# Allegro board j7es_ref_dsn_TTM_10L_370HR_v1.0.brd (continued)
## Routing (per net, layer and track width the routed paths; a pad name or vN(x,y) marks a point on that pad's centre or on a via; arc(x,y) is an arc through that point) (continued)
MCU_OSPI0_D2: length 34.5
  TOP w0.229: R161.2 U24.C4 v1(78.75,45.46) ; v1(94.25,64.95) 94.65,65.35 U9.G20
  L7-SIGNAL w0.097: v1(94.25,64.95) 93.88,65.31 93.13,65.31 93.02,65.19 93.02,59.22 90.81,57.01 84.45,57.01 78.34,50.9 78.34,45.87 v1(78.75,45.46)
  BOTTOM w0.229: U24.C4 v1(78.75,45.46)
MCU_OSPI0_D3: length 37.6
  TOP w0.229: v1(78.75,44.46) 78.22,43.93 77.75,43.93 77.62,43.8 R158.2 ; v1(94.25,64.15) 94.25,64.15 U9.F20
  L9-SIGNAL w0.097: v1(78.75,44.46) 79.28,43.93 82.04,43.93 82.42,43.55 84.36,43.55 86.26,45.46 89.79,45.46 96.01,51.68 96.01,58.36 95.45,58.92 95.45,63.49 95.16,63.78 94.61,63.78 v1(94.25,64.15)
  BOTTOM w0.229: U24.D4 v1(78.75,44.46)
MCU_OSPI0_D4: length 35.3
  TOP w0.229: U9.F21 93.45,64.15 v1(93.45,64.15) ; R162.2 77,44.46 v1(77.75,44.46)
  L7-SIGNAL w0.097: v1(77.75,44.46) 78.23,44.95 78.87,44.95 79.25,45.33 79.25,48 80.64,49.39 84.84,49.39 85.22,49.01 90.3,49.01 92.96,51.68 92.96,58.28 93.83,59.14 93.83,63.8 93.48,64.15 v1(93.45,64.15)
  BOTTOM w0.229: U24.D5 v1(77.75,44.46)
MCU_OSPI0_D5: length 31
  TOP w0.229: U9.E21 93.85,63.75 v1(93.45,63.35) ; v1(79.75,43.46) 79.75,42.81 R156.2
  L5-PWR/GND w0.097: v1(93.45,63.35) 93.01,62.9 93.01,61.9 93.01,61.89 93.01,61.6 93.01,61.6 93.01,59.21 89.75,55.95 89.75,53.75 89.28,53.29 89.28,50.79 85.72,47.23 85.72,44.31 84.45,43.04 80.17,43.04 v1(79.75,43.46)
  BOTTOM w0.229: U24.E3 v1(79.75,43.46)
MCU_OSPI0_D6: length 28
  TOP w0.229: v1(92.65,60.95) 93.05,61.35 U9.B22 ; R150.2 81.34,44.06 v1(80.75,43.46)
  L5-PWR/GND w0.097: v1(92.65,60.95) 92.21,60.5 92.21,59.18 89.41,56.38 89.41,53.97 88.77,53.33 88.77,50.79 85.34,47.36 85.34,44.57 84.2,43.42 82.8,43.42 82.3,43.93 81.22,43.93 v1(80.75,43.46)
  BOTTOM w0.229: U24.E2 v1(80.75,43.46)
MCU_OSPI0_D7: length 33.5
  TOP w0.229: v1(81.75,43.46) 81.75,43.06 81.89,42.91 82.38,42.91 R151.2 ; v1(93.45,64.95) 93.45,64.95 U9.G21
  L7-SIGNAL w0.097: v1(81.75,43.46) 82.14,43.46 82.24,43.36 86.04,43.36 93.85,51.17 93.85,56.5 95.48,58.14 95.48,62.63 95.2,62.91 94.97,62.91 94.68,63.19 94.68,63.5 94.74,63.56 94.74,63.87 94.61,64 94.61,64.3 94.4,64.51 93.88,64.51 v1(93.45,64.95)
  BOTTOM w0.229: U24.E1 v1(81.75,43.46)
MCU_OSPI0_DQS: length 22.8
  TOP w0.229: v1(93.45,62.55) 93.45,62.55 U9.D21 ; R152.2 84.11,47.87 v1(84.71,47.27)
  L2-SIGNAL w0.097: v1(84.71,47.27) 84.71,50.47 85.79,51.55 87.69,51.55 89.66,53.52 89.66,55.93 91.06,57.33 91.06,59.17 91.48,59.6 91.48,60.3 91.7,60.51 92,60.51 92.28,60.79 92.28,61.1 92.5,61.31 92.8,61.31 93.08,61.59 93.08,62.18 v1(93.45,62.55)
MCU_OSPI0_ECC_FAIL: length 23.2
  TOP w0.229: U9.B23 91.85,60.95 v1(91.85,60.95) ; R164.1 v1(75.55,47.73)
  L9-SIGNAL w0.097: v1(75.55,47.73) 75.55,48.62 85.22,58.28 89.79,58.28 91.44,59.93 91.44,60.54 v1(91.85,60.95)
MCU_OSPI0_LBCLKO: length 20.4
  L9-SIGNAL w0.097: v1(92.38,56.8) 93.05,56.13 93.05,54.43 92.46,53.84 85.85,53.84 81.25,49.23 v1(81.25,48.09)
  BOTTOM w0.229: R264.2 92.39,56.79 v1(92.38,56.8) ; U24.B1 v1(81.25,48.09) 81.28,48.12 R3140.1
MCU_OSPI0_RESET_OUT0: length 1.4
  TOP w0.229: R137.1 R108.1
MCU_OSPI0_RESET_OUT0_R: length 2.7
  TOP w0.229: R108.2 70.48,48.2 R114.1 70.56,47.67 70.61,47.61 U18.2
MCU_OSPI1_CLK: length 0.9
  BOTTOM w0.229: R240.2 79.97,61.67 TPX68.1
MCU_OSPI1_CLK_R: length 13.7
  TOP w0.229: U9.F22 93.05,64.55 v1(92.65,64.15)
  L9-SIGNAL w0.097: v1(92.65,64.15) 92.26,64.54 88.46,64.54 88.22,64.3 88.22,63.99 88,63.78 83.47,63.78 v1(81.91,62.22)
  BOTTOM w0.229: R240.1 v1(81.91,62.22)
MCU_OSPI1_CS0: length 39.3
  TOP w0.229: U9.C22 92.66,61.75 v1(92.65,61.75)
  L7-SIGNAL w0.097: v1(92.65,61.75) 92.65,61.68 92.21,61.24 92.21,59.18 90.42,57.39 84.2,57.39 80.39,53.58 76.2,53.58 73.53,50.92 62.74,50.92 62.23,50.41 62.23,49.14 TPX95.1
MCU_OSPI1_D0: length 31.3
  TOP w0.229: U9.D22 93.05,62.95 v1(92.65,62.55)
  L7-SIGNAL w0.097: v1(92.65,62.55) 92.21,62.11 90.9,62.11 90.68,61.9 90.68,59.18 89.75,58.24 83.79,58.24 80,54.45 75.79,54.45 73.53,52.19 TPX168.1
MCU_OSPI1_D1: length 33.8
  TOP w0.229: v1(92.65,64.95) 93.05,65.35 U9.G22
  L9-SIGNAL w0.097: v1(92.65,64.95) 92.52,64.95 92.09,65.38 88.5,65.38 88.22,65.1 88.22,64.79 88,64.58 83.69,64.58 72.06,52.95 66.04,52.95 TPX93.1
MCU_OSPI1_D2: length 34.1
  TOP w0.229: v1(91.85,62.55) 92.25,62.95 U9.D23
  L9-SIGNAL w0.097: v1(91.85,62.55) 91.41,62.11 90.9,62.11 90.63,61.84 90.63,59.98 89.44,58.79 84.66,58.79 75.52,49.65 66.55,49.65 TPX21.1
MCU_OSPI1_D3: length 39.9
  TOP w0.229: v1(91.85,61.75) 91.85,61.75 U9.C23
  L7-SIGNAL w0.097: v1(91.85,61.75) 91.85,61.66 91.44,61.25 91.44,59.17 90.04,57.77 83.95,57.77 80.19,54.02 76,54.02 73.14,51.16 61.46,51.16 60.96,50.66 60.96,49.14 TPX121.1
MCU_PERIPH_RSTZ: length 1.5
  TOP w0.229: R109.1 TPX67.1
MCU_PERIPH_RSTZ_R: length 2.6
  TOP w0.229: R109.2 71.63,48.2 R115.1 71.55,47.67 71.56,47.65 U18.1
MCU_PORZ: length 31.1
  TOP w0.229: U9.H23 92.25,66.15 v1(91.85,65.75)
  L5-PWR/GND w0.097: TPX166.1 66.29,59.43 76.2,59.43 79.38,62.6 83.31,62.6 83.82,62.09 86.89,62.09 86.98,62.19 88,62.19 88.21,62.4 88.21,62.61 88.58,62.99 88.8,62.99 89.09,63.28 89.09,63.49 89.3,63.7 89.51,63.7 89.81,64 89.81,64.21 90.1,64.5 90.31,64.5 90.61,64.8 90.61,65.01 90.9,65.3 91.41,65.3 v1(91.85,65.75)
MCU_PORZ_OUT: length 54
  TOP w0.229: R124.1 v1(40.77,52.82) ; v1(87.85,60.95) 87.85,60.95 U9.B28
  L2-SIGNAL w0.097: v1(40.77,52.82) 44.07,52.82 45.72,51.17 48.13,51.17 50.26,53.29 55.21,53.29 56.52,54.6 78.87,54.6 84.84,60.57 87.47,60.57 v1(87.85,60.95)
MCU_RESETSTATZ: length 54.3
  TOP w0.229: TP116.1 TPX92.1 R113.1 ; U9.C27 89.05,62.15 v1(88.65,61.75)
  L4-SIGNAL w0.097: TPX92.1 41.78,60.57 54.55,60.57 54.87,60.25 59.75,60.25 60.83,61.33 74.42,61.33 75.06,60.7 84.07,60.7 84.75,61.38 88.26,61.38 88.63,61.75 v1(88.65,61.75)
MCU_RESETZ: length 56.1
  TOP w0.229: v1(87.85,62.55) 87.85,62.55 U9.D28
  L2-SIGNAL w0.097: TPX193.1 36.55,53.94 53.82,53.94 54.35,54.47 55.37,54.47 56.01,55.11 78.42,55.11 85.17,61.85 86.64,61.85 86.9,62.11 87.41,62.11 v1(87.85,62.55)
MCU_RGMII1_INT#: length 29.4
  TOP w0.229: U9.E25 90.65,63.75 v1(90.25,63.35)
  L9-SIGNAL w0.097: v1(90.25,63.35) 89.85,63.74 88.46,63.74 88.22,63.5 88.22,63.19 88,62.98 84.6,62.98 74.19,52.57 67.99,52.57 67.98,52.58 66.94,52.58 TPX48.1
MCU_RGMII1_RD0: length 35.8
  TOP w0.229: U9.B24 91.45,61.35 v1(91.05,60.95)
  L5-PWR/GND w0.097: TPX80.1 63.34,47.07 66.51,47.07 67.69,48.25 67.69,48.8 69.17,50.28 76.33,50.28 83.31,57.27 88.39,57.27 90.61,59.49 90.61,60.51 v1(91.05,60.95)
MCU_RGMII1_RD1: length 34.3
  TOP w0.229: v1(91.05,60.14) 91.05,60.14 U9.A24
  L5-PWR/GND w0.097: v1(91.05,60.14) 91.05,59.16 88.77,56.89 83.57,56.89 76.33,49.65 68.83,49.65 68.07,48.88 68.07,48.12 66.81,46.86 66.01,46.86 66.01,46.86 65.49,46.86 65.49,46.86 64.4,46.86 TPX87.1
MCU_RGMII1_RD2: length 36.4
  TOP w0.229: v1(91.05,62.55) 91.05,62.55 U9.D24
  L5-PWR/GND w0.097: TPX88.1 63.25,47.87 65.66,47.87 65.91,48.12 65.91,48.76 66.42,49.27 67.06,49.27 71.12,53.33 77.09,53.33 82.17,58.41 87.63,58.41 89.09,59.87 89.09,60.29 89.3,60.5 89.72,60.5 89.89,60.67 89.89,61.09 90.1,61.3 90.4,61.3 90.44,61.34 90.44,61.38 90.69,61.63 90.69,62.19 v1(91.05,62.55)
MCU_RGMII1_RD3: length 35.5
  TOP w0.229: U9.A25 90.25,60.14 v1(90.25,60.14)
  L5-PWR/GND w0.097: TPX107.1 62.28,47.28 66.29,47.28 67.26,48.26 67.26,48.71 69.27,50.72 76.25,50.72 83.19,57.65 88.14,57.65 90.25,59.76 v1(90.25,60.14)
MCU_RGMII1_RX_CTL: length 32.7
  TOP w0.229: U9.C25 90.65,62.15 v1(90.25,61.75)
  L5-PWR/GND w0.097: TPX61.1 65.28,49.65 66.93,49.65 71.37,54.09 77.22,54.09 82.04,58.92 87.25,58.92 88.27,59.93 88.27,60.27 88.5,60.5 88.71,60.5 89.01,60.8 89.01,61.06 89.34,61.39 89.89,61.39 v1(90.25,61.75)
MCU_RGMII1_RXC: length 38.6
  TOP w0.229: U9.C24 91.05,61.75 v1(91.05,61.75)
  L5-PWR/GND w0.097: TPX64.1 61.34,47.61 65.7,47.61 66.12,48.04 66.12,48.67 66.38,48.93 67.02,48.93 70.07,51.99 76.63,51.99 82.68,58.03 87.84,58.03 89.81,59.99 89.81,60.22 90.1,60.51 90.32,60.51 90.61,60.79 90.61,61.31 v1(91.05,61.75)
MCU_RGMII1_TD0: length 59.8
  TOP w0.229: U9.B25 90.65,61.35 v1(90.25,60.95)
  L2-SIGNAL w0.097: v1(90.25,60.95) 89.88,60.58 89.88,58.38 87.76,56.25 86.11,56.25 82.68,52.82 59.69,52.82 57.66,50.79 51.05,50.79 49.53,49.27 37.72,49.27 TPX106.1
MCU_RGMII1_TD1: length 59.7
  TOP w0.229: v1(89.45,60.14) 89.85,60.54 U9.A26
  L2-SIGNAL w0.097: v1(89.45,60.14) 89.45,58.7 87.88,57.14 85.09,57.14 81,53.05 59.41,53.05 57.4,51.04 50.67,51.04 49.15,49.52 38.61,49.52 37.97,50.15 36.58,50.15 TPX108.1
MCU_RGMII1_TD2: length 61.2
  TOP w0.229: v1(88.65,60.14) 89.05,60.54 U9.A27
  L2-SIGNAL w0.097: TPX131.1 34.67,50.79 38.23,50.79 38.86,50.15 48.64,50.15 50.17,51.68 55.24,51.68 56.64,53.08 57.79,53.08 58.29,53.58 80.52,53.58 84.71,57.77 87.38,57.77 88.65,59.05 v1(88.65,60.14)
MCU_RGMII1_TD3: length 55.2
  TOP w0.229: v1(87.85,60.14) 87.85,60.14 U9.A28
  L2-SIGNAL w0.097: v1(87.85,60.14) 85.05,60.14 79.25,54.35 56.9,54.35 54.88,52.33 49.8,52.33 48.39,50.92 45.34,50.92 44.83,51.42 40.77,51.42 40.64,51.55 TPX187.1
MCU_RGMII1_TX_CTL: length 58.5
  TOP w0.229: v1(88.65,60.95) 88.65,60.95 U9.B27
  L2-SIGNAL w0.097: TPX156.1 36.47,51.15 44.47,51.15 45.08,50.54 48.51,50.54 50.08,52.11 55.16,52.11 57.02,53.96 80.26,53.96 84.58,58.28 87,58.28 88.27,59.55 88.27,60.56 v1(88.65,60.95)
MCU_RGMII1_TXC: length 61.5
  TOP w0.229: U9.B26 89.85,61.35 v1(89.45,60.95)
  L2-SIGNAL w0.097: TPX105.1 35.69,50.54 38.1,50.54 38.86,49.77 48.77,49.77 50.42,51.42 57.4,51.42 59.31,53.33 80.64,53.33 84.71,57.39 87.63,57.39 89.01,58.78 89.01,60.51 v1(89.45,60.95)
MCU_SAFETY_ERRZ: length 1.5
  TOP w0.229: U27.18 126.59,99.15 126.49,99.05 ; R120.2 v1(84.58,53.84)
MCU_UART0_CTS#: length 53.9
  TOP w0.229: U9.H29 87.05,65.75 v1(87.05,65.75)
  L2-SIGNAL w0.097: TPX214.1 43.81,57.27 43.94,57.14 48.89,57.14 49.56,57.8 54.64,57.8 54.99,58.16 61.15,58.16 64.2,61.2 78.74,61.2 80.9,63.36 83.44,63.36 85.82,65.75 v1(87.05,65.75)
MCU_UART0_RTS#: length 29.3
  TOP w0.229: U9.J27 89.05,66.95 v1(88.65,66.55)
  L5-PWR/GND w0.097: TPX215.1 63.88,61.58 75.69,61.58 77.64,63.53 83.48,63.53 85.34,65.39 88,65.39 88.21,65.6 88.21,66.1 v1(88.65,66.55)
MCU_UART0_RXD: length 56.5
  TOP w0.229: v1(87.85,65.75) 87.85,65.75 U9.H28
  L2-SIGNAL w0.097: v1(87.85,65.75) 87.48,66.11 85.68,66.11 83.31,63.74 80.9,63.74 78.74,61.58 61.72,61.58 59.31,59.17 48.64,59.17 46.99,57.52 45.15,57.52 45.13,57.5 44.79,57.5 44.77,57.52 38.73,57.52 38.35,57.9 36.7,57.9 TPX258.1
MCU_UART0_TXD: length 54.3
  TOP w0.229: v1(87.05,64.95) 87.45,65.35 U9.G29
  L2-SIGNAL w0.097: TPX319.1 45.24,56 45.49,56.25 53.34,56.25 53.47,56.12 54.1,56.12 54.82,56.84 61.93,56.84 62.23,57.14 62.23,57.52 62.74,58.03 75.56,58.03 77.6,60.06 80.31,60.06 82.85,62.6 83.69,62.6 86.04,64.95 v1(87.05,64.95)
MDIO0_MDC: length 64.4
  TOP w0.191: U9.V24 91.45,74.15 v1(91.05,74.55)
  TOP w0.229: v1(52.7,45.46) 51.94,44.69 49.64,44.69 49.61,44.67 U2011.1
  L5-PWR/GND w0.097: v1(91.05,74.55) 90.7,74.2 90.7,73.16 89.81,72.27 89.81,72 89.55,71.74 83.95,71.74 81.96,69.76 62.83,69.76 59.99,66.92 58.93,66.92 58.29,66.28 58.29,58.92 56.9,57.52 56.9,54.35 56.52,53.96 56.52,49.27 v1(52.7,45.46)
MDIO0_MDIO: length 66.4
  TOP w0.191: U9.V26 89.85,74.15 v1(89.45,74.55)
  TOP w0.229: U2011.36 v1(50.9,43.77)
  L5-PWR/GND w0.097: v1(89.45,74.55) 89.01,74.11 86.56,74.11 86.11,73.65 80.91,73.65 79.64,72.38 76.96,72.38 76.45,72.89 70.74,72.89 69.47,74.16 60.32,74.16 56.13,69.97 56.13,59.81 54.86,58.54 54.86,55.11 51.58,51.83 51.58,48.02 50.93,47.36 50.93,44.18 50.9,44.15 v1(50.9,43.77)
MLB0_MLBCLK_N: length 63.6
  TOP w0.122: v1(109.45,80.15) 109.05,79.75 U9.AE2
  L9-SIGNAL w0.076: v1(109.45,80.15) 109.45,80.1 109.67,79.88 109.78,79.88 109.88,79.97 109.88,80.3 110.08,80.51 110.52,80.51 110.75,80.74 110.75,80.95 113.3,83.51 122.26,83.51 122.69,83.94 127.81,83.94 128.57,83.17 131.73,83.17 132.29,82.62 137.85,82.62 141.91,78.55 162.98,78.55 164.13,79.7 167.06,79.7 167.13,79.77 TPX351.1
MLB0_MLBCLK_P: length 63.4
  TOP w0.122: U9.AD2 109.05,78.95 v1(109.45,79.35)
  L9-SIGNAL w0.076: v1(109.45,79.35) 109.64,79.35 110.06,79.77 110.39,79.77 110.62,80 110.62,80.32 110.95,80.65 110.95,80.87 113.39,83.3 122.34,83.3 122.77,83.73 127.72,83.73 128.49,82.97 131.65,82.97 132.21,82.41 137.76,82.41 141.83,78.35 163.07,78.35 164.21,79.49 166.88,79.49 167.13,79.24 TPX352.1
MLB0_MLBDAT_N: length 66.3
  TOP w0.122: U9.AD3 108.25,78.95 v1(108.65,79.35)
  L9-SIGNAL w0.076: v1(108.65,79.35) 109.01,79.71 109.01,80.39 109.03,80.41 109.06,80.47 109.06,80.48 109.1,80.55 109.14,80.59 109.6,80.59 109.81,80.8 109.81,81.1 109.91,81.19 109.99,81.19 110.2,81.39 110.4,81.39 110.61,81.6 110.61,81.61 110.65,81.65 110.65,81.78 114.08,85.21 127.86,85.21 129.2,83.86 137.58,83.86 142.21,79.24 162.05,79.24 164.87,82.06 167.06,82.06 167.13,81.98 TPX333.1
MLB0_MLBDAT_P: length 68.2
  TOP w0.122: U9.AC3 108.25,78.15 v1(108.65,78.55)
  L9-SIGNAL w0.076: TPX334.1 167.13,82.34 167.06,82.26 164.79,82.26 161.97,79.44 142.29,79.44 137.67,84.06 129.29,84.06 127.94,85.41 114,85.41 110.55,81.96 110.55,81.96 110.4,82.11 110.11,82.11 109.9,81.9 109.9,81.6 109.91,81.59 109.91,81.4 109.82,81.4 109.73,81.31 109.31,81.31 109.1,81.1 109.1,80.8 109.09,80.8 109.06,80.8 108.93,80.67 108.9,80.61 108.88,80.57 108.87,80.57 108.84,80.51 108.51,80.51 108.3,80.3 108.3,78.91 v1(108.65,78.55)
MLB0_MLBSIG_N: length 62
  TOP w0.122: v1(110.25,78.55) 109.85,78.15 U9.AC1
  L9-SIGNAL w0.076: v1(110.25,78.55) 110.55,78.85 110.79,78.85 111.25,79.31 111.25,80.12 112.4,81.27 121.95,81.27 122.83,82.15 131.17,82.15 131.61,81.7 137.2,81.7 141.44,77.46 162.69,77.46 163.17,76.98 167.06,76.98 167.13,76.9 TPX354.1
MLB0_MLBSIG_P: length 62
  TOP w0.122: v1(110.25,79.35) 109.85,78.95 U9.AD1
  L9-SIGNAL w0.076: TPX353.1 167.13,77.26 167.06,77.18 163.25,77.18 162.77,77.66 141.53,77.66 137.29,81.9 131.7,81.9 131.25,82.35 122.75,82.35 121.87,81.47 112.32,81.47 111.05,80.2 111.05,79.4 110.7,79.05 110.55,79.05 v1(110.25,79.35)
MMC0_CALPAD: length 1.4
  TOP w0.191: U9.AE1 109.85,79.75 v1(110.25,80.15)
  BOTTOM w0.229: R204.2 110.95,80.43 110.53,80.43 v1(110.25,80.15)
MMC0_CLK: length 41
  TOP w0.191: U9.AF1 110.25,80.94 v1(110.25,80.95)
  L5-PWR/GND w0.097: v2(146.81,85.97) 144.65,83.81 122.68,83.81 122.05,83.17 121.96,83.17 121.96,83.17 121.79,83.17 121.79,83.17 119.38,83.17 117.6,81.4 111.51,81.4 111.06,80.95 v1(110.25,80.95)
  BOTTOM w0.127: R1204.2 R1203.1 v2(146.81,85.97)
MMC0_CMD: length 43.7
  TOP w0.191: v1(108.65,80.15) 108.65,80.14 U9.AE3
  TOP w0.229: U1017.P5 v2(147.66,86.21)
  L5-PWR/GND w0.097: v2(147.66,86.21) 143.74,82.29 121.54,82.29 120.4,81.14 111.72,81.14 111.08,80.51 109.01,80.51 v1(108.65,80.15)
  BOTTOM w0.127: R1200.2 147.7,86.16 v2(147.66,86.21)
MMC0_DAT0: length 47.4
  TOP w0.191: v1(109.45,81.75) 109.45,81.74 U9.AG2
  TOP w0.229: U1017.K2 v2(151.66,89.21)
  L5-PWR/GND w0.097: v1(109.45,81.75) 109.86,82.16 111,82.16 114.13,85.29 123.87,85.29 124.55,85.97 143.76,85.97 v1(146.56,88.76)
  L9-SIGNAL w0.097: v1(146.56,88.76) 151.21,88.76 v2(151.66,89.21)
  BOTTOM w0.127: v2(151.66,89.21) 151.64,89.23 151.64,90.03
MMC0_DAT1: length 44.3
  TOP w0.191: v1(110.25,82.55) 110.25,82.54 U9.AH1
  TOP w0.229: U1017.N2 v2(148.66,89.21)
  L5-PWR/GND w0.097: v1(110.25,82.55) 111.01,82.55 115.44,86.98 124.08,86.98 124.84,86.22 143.25,86.22 146.74,89.71 148.16,89.71 v2(148.66,89.21)
  BOTTOM w0.127: R1197.2 148.72,89.27 v2(148.66,89.21)
MMC0_DAT2: length 50.8
  TOP w0.191: U9.AG3 108.65,81.74 v1(108.65,81.75)
  TOP w0.229: U1017.K3 v2(151.66,88.21)
  L5-PWR/GND w0.097: v1(108.65,81.75) 109.1,82.19 109.1,82.7 109.3,82.91 109.59,82.91 109.98,83.3 111,83.3 115.19,87.49 125.3,87.49 125.43,87.37 135.89,87.37 136.53,88 143.51,88 146.05,90.54 150.4,90.54 151.13,89.81 151.13,88.74 v2(151.66,88.21)
  BOTTOM w0.127: 151.64,87.37 151.64,88.19 v2(151.66,88.21)
MMC0_DAT3: length 50.4
  TOP w0.191: U9.AF4 107.85,80.94 v1(107.85,80.95)
  TOP w0.229: U1017.N3 v2(148.66,88.21)
  L5-PWR/GND w0.097: v1(148.08,90.92) 145.92,90.92 143.38,88.38 130.68,88.38 130.01,87.7 115.1,87.7 114.98,87.58 111.21,83.81 109.35,83.81 109.01,83.47 109.01,83.2 108.8,82.99 108.53,82.99 108.21,82.67 108.21,81.31 v1(107.85,80.95)
  L7-SIGNAL w0.097: v2(148.66,88.21) 148.08,88.79 v1(148.08,90.92)
  BOTTOM w0.127: v2(148.66,88.21) 148.72,88.15 R1201.2
MMC0_DAT4: length 45.2
  TOP w0.191: U9.AE5 107.05,80.14 v1(107.05,80.15)
  TOP w0.229: U1017.N8 v2(148.66,82.2)
  L5-PWR/GND w0.097: v1(107.05,80.15) 107.5,79.71 110.71,79.71 111.89,80.89 120.52,80.89 121.67,82.03 145.16,82.03 145.41,81.78 148.23,81.78 v2(148.66,82.2)
  BOTTOM w0.127: v2(148.66,82.2) 148.84,82.39 R1196.2
MMC0_DAT5: length 55.9
  TOP w0.191: v1(108.65,80.95) 108.65,80.94 U9.AF3
  TOP w0.229: U1017.K8 v2(151.66,82.2)
  L5-PWR/GND w0.097: v1(108.65,80.95) 109.1,81.39 109.1,81.9 109.3,82.11 109.55,82.11 109.9,82.45 109.9,82.83 110.05,82.99 111.15,82.99 115.4,87.24 125.26,87.24 125.34,87.16 136.61,87.16 137.2,87.75 144.02,87.75 146.43,90.16 148.84,90.16 149.22,89.78 149.22,88.51 150.11,87.62 150.11,85.71 151.66,84.17 v2(151.66,82.2)
  BOTTOM w0.127: R1190.2 151.51,82.35 v2(151.66,82.2)
MMC0_DAT6: length 47.7
  TOP w0.191: v1(110.25,81.75) 110.25,81.74 U9.AG1
  TOP w0.229: U1017.N9 v2(148.66,81.2)
  L5-PWR/GND w0.097: v1(146.81,87.11) 145.8,87.11 144.4,85.71 124.59,85.71 123.96,85.08 114.3,85.08 110.97,81.75 v1(110.25,81.75)
  L7-SIGNAL w0.097: v2(148.66,81.2) 148.21,81.65 148.21,84.57 147.22,85.56 147.22,86.71 v1(146.81,87.11)
  BOTTOM w0.127: v2(148.66,81.2) 148.59,81.14 R1198.2
MMC0_DAT7: length 50.5
  TOP w0.191: U9.AF2 109.45,80.94 v1(109.45,80.95)
  TOP w0.229: U1017.K9 v2(151.66,81.2)
  L5-PWR/GND w0.097: v1(109.45,80.95) 109.81,81.31 110.91,81.31 111.25,81.65 117.35,81.65 119.08,83.39 121.88,83.39 122.55,84.06 124.46,84.06 125.35,84.95 144.53,84.95 146.18,86.6 147.48,86.6 147.49,86.61 147.83,86.61 149.35,85.08 149.35,82.54 150.24,81.65 151.21,81.65 v2(151.66,81.2)
  BOTTOM w0.127: v2(151.66,81.2) 151.64,81.18 R1191.2
MMC0_DS: length 51.2
  TOP w0.191: U9.AE4 107.85,80.14 v1(107.85,80.15)
  L5-PWR/GND w0.097: v1(107.85,80.15) 107.5,80.51 107.5,82.72 107.77,82.99 108,82.99 108.21,83.2 108.21,83.44 108.97,84.19 110.72,84.19 114.45,87.91 129.73,87.91 130.42,88.61 142.85,88.61 145.54,91.3 v1(150.88,91.3)
  BOTTOM w0.229: R3142.1 v1(150.88,91.3)
MMC1_CLK: length 23.7
  TOP w0.229: U9.P25 90.65,70.95 v1(90.25,70.55)
  L7-SIGNAL w0.097: TPX62.1 70.99,68.32 71.63,68.95 77.95,68.95 78.79,68.11 82.6,68.11 84.58,70.09 86.88,70.09 86.9,70.11 87.2,70.11 87.22,70.09 87.68,70.09 87.7,70.11 88,70.11 88.02,70.09 88.48,70.09 88.5,70.11 88.8,70.11 88.82,70.09 89.28,70.09 89.3,70.11 89.6,70.11 89.62,70.09 89.79,70.09 90.01,70.32 90.02,70.32 v1(90.25,70.55)
MMC1_CMD: length 22.5
  TOP w0.229: U9.R29 87.45,71.75 v1(87.05,71.35)
  L7-SIGNAL w0.097: TPX86.1 69.72,68.19 71.12,69.59 83.06,69.59 84.82,71.35 v1(87.05,71.35)
MMC1_DAT0: length 32.9
  TOP w0.229: U9.R24 91.06,71.35 v1(91.05,71.35)
  L7-SIGNAL w0.097: TPX136.1 66.55,66.79 71.46,71.7 81.62,71.7 82.64,72.72 86.74,72.72 86.74,72.72 90.34,72.72 90.68,72.38 90.68,71.72 v1(91.05,71.35)
MMC1_DAT1: length 26
  TOP w0.229: U9.P24 91.06,70.55 v1(91.05,70.55)
  L7-SIGNAL w0.097: TPX162.1 70.48,65.39 70.48,68.32 71.5,69.33 83.19,69.33 84.77,70.91 90.68,70.91 v1(91.05,70.55)
MMC1_DAT2: length 27
  TOP w0.229: U9.R25 90.65,71.75 v1(90.25,71.35)
  L7-SIGNAL w0.097: TPX111.1 69.09,66.79 69.09,68.82 71.75,71.49 82.93,71.49 83.82,72.38 86.61,72.38 86.75,72.51 89.6,72.51 89.82,72.3 89.82,71.78 v1(90.25,71.35)
MMC1_DAT3: length 26.1
  TOP w0.229: U9.R26 89.46,71.35 v1(89.45,71.35)
  L7-SIGNAL w0.097: TPX85.1 69.47,65.9 69.47,68.57 70.74,69.84 82.68,69.84 84.55,71.72 89.08,71.72 v1(89.45,71.35)
MMC1_SDCD/PCIE2_CLKREQN: length 35.9
  TOP w0.229: R86.2 TPX189.1 ; U9.P23 92.25,70.95 v1(91.85,70.55)
  BOTTOM w0.127: v1(91.85,70.55) 91.45,70.15 83.24,70.15 82.3,69.2 61.98,69.2 61.37,69.81 58.58,69.81 TPX189.1
Net_12: length 0.6
  TOP w0.191: 105.85,68.55 v1(106.25,68.15)
Net_13: length 0.6
  TOP w0.191: 105.85,70.15 v1(106.25,69.75)
Net_14: length 0.6
  TOP w0.229: 90.65,70.14 90.25,69.75 v1(90.25,69.75)
Net_15: length 0.6
  TOP w0.229: 89.05,71.74 88.66,71.35 v1(88.65,71.35)
Net_16: length 0.6
  TOP w0.191: 87.45,82.94 v1(87.05,83.34)
Net_17: length 0.6
  TOP w0.229: 89.85,70.94 89.85,70.95 v1(89.45,70.55)
Net_18: length 0.6
  TOP w0.191: v1(107.85,79.35) 107.45,78.95 107.45,78.94
Net_19: length 0.6
  TOP w0.229: v1(95.85,63.35) 96.25,63.74 96.25,63.74
Net_20: length 0.6
  TOP w0.229: 96.25,64.54 96.25,64.55 v1(95.85,64.15)
Net_21: length 0.6
  TOP w0.229: v1(103.05,64.95) 102.65,65.35 102.65,65.34
Net_22: length 0.6
  TOP w0.229: 101.85,64.54 v1(102.25,64.15)
Net_23: length 0.6
  TOP w0.191: 105.85,64.54 v1(106.25,64.15)
Net_24: length 0.6
  TOP w0.191: 105.85,63.74 v1(106.25,63.35)
Net_25: length 0.6
  TOP w0.229: v1(103.85,64.95) 103.45,65.35 103.45,65.34
Net_26: length 0.6
  TOP w0.229: 102.65,64.54 v1(103.05,64.15)
Net_33: length 2.9
  TOP w0.119: v1(118.49,21.52) 118.32,21.34 117.87,21.34 117.58,21.63 117.01,21.63 116.73,21.35 116.73,20.74 116.6,20.6
Net_34: length 2.7
  TOP w0.119: 117.15,20.6 117,20.76 117,21.24 117.11,21.36 117.47,21.36 117.76,21.08 118.37,21.08 118.49,20.96 v1(118.49,20.67)
Net_256: length 4.5
  TOP w0.119: 116.6,19.38 116.64,19.33 arc(116.71,19.24) 116.73,19.13 116.73,18.85 arc(116.71,18.74) 116.64,18.64 116.31,18.31 116.67,17.96 arc(116.69,17.93) 116.71,17.9 arc(116.71,17.88) 116.71,17.86 116.71,17.75 arc(116.82,17.48) 117.09,17.37 117.67,17.37 arc(117.75,17.34) 117.79,17.25 117.79,17.04 arc(117.78,17) 117.75,16.96 117.3,16.5 arc(117.24,16.41) 117.22,16.31
Net_257: length 4.5
  TOP w0.119: 117.15,19.38 117.13,19.35 arc(117.03,19.2) 116.99,19.03 116.99,18.86 arc(117.02,18.73) 117.09,18.62 117.37,18.35 117.37,18.31 117.01,17.96 arc(116.98,17.91) 116.97,17.86 116.97,17.75 arc(117,17.67) 117.09,17.63 117.67,17.63 arc(117.94,17.52) 118.05,17.25 118.05,16.98 arc(118.05,16.93) 118.06,16.88 arc(118.1,16.79) 118.16,16.72 118.57,16.31
Net_894: length 0.7
  BOTTOM w0.229: 77.25,46.96 v1(77.75,46.46)
Net_952: length 0.6
  TOP w0.191: v1(91.85,76.95) 92.25,76.55 92.25,76.54
Net_956: length 0.7
  TOP w0.229: 74.7,110.42 v1(74.7,109.69)
NTRST: length 5.5
  TOP w0.229: J1011.9 53.68,57.1 v1(53.85,57.27)
  BOTTOM w0.229: v1(53.85,57.27) 53.09,57.27 52.45,56.63 RJ1025.3
OSC1_XI: length 10
  TOP w0.229: v1(87.05,70.55) 87.06,70.55 U9.P29 ; v1(79.38,73.23) R67.1
  L2-SIGNAL w0.097: v1(87.05,70.55) 86.68,70.55 86.5,70.73 84.51,70.73 83.12,72.13 80.48,72.13 v1(79.38,73.23)
OSC1_XO: length 18.6
  TOP w0.229: U9.P27 89.05,70.95 v1(88.65,70.55)
  L2-SIGNAL w0.097: v1(71.88,70.56) 73.06,71.74 82.93,71.74 84.2,70.47 86.36,70.47 86.66,70.18 88.28,70.18 v1(88.65,70.55)
OSPI0_ECC_FAIL/MCU_HYPERBUS0_IN: length 3.2
  TOP w0.229: v1(77.75,47.46) 77.28,47.46 77.01,47.74 R164.2
  BOTTOM w0.229: v1(77.75,47.46) U24.A5 77.25,48.37 77.22,48.4 R3139.1
OSPI/HYPER_MUX_SEL: length 58
  TOP w0.229: v1(88.65,64.95) 89.05,65.35 U9.G27
  L2-SIGNAL w0.097: v1(88.65,64.95) 88.21,64.51 86.11,64.51 78.15,56.55 55.34,56.55 53.89,55.11 52.7,55.11 52.32,55.49 48.54,55.49 48.27,55.22 47.51,55.22 46.99,55.74 44.8,55.74 44.55,55.49 36.58,55.49 TPX238.1
OSPI_DQS_R: length 4.8
  TOP w0.229: R152.1 82.26,47.5 81.76,47.01 80.68,47.01 80.32,46.64 80.32,46.03 v1(79.75,45.46)
  BOTTOM w0.229: U24.C3 v1(79.75,45.46)
OSPI_RST#: length 1.8
  TOP w0.229: U18.4 v1(69.66,42.95)
  BOTTOM w0.229: U24.A4 v1(78.75,47.46)
PCIE0_RX0_N: length 43.2
  TOP w0.267: U9.AH19 v1(95.05,82.55)
  L9-SIGNAL w0.127: TPX379.1 89.69,121.76 arc(89.84,121.53) 89.89,121.27 89.89,116.94 arc(90.15,115.65) 90.88,114.56 93.56,111.88 arc(94.04,111.16) 94.21,110.3 94.21,95.89 arc(94.15,95.61) 94,95.37 93.59,94.96 arc(93.28,94.5) 93.17,93.95 93.17,88.57 arc(93.26,88.13) 93.51,87.75 93.66,87.6 arc(93.88,87.27) 93.95,86.89 93.95,85.01 arc(94.04,84.57) 94.29,84.19 94.41,84.07 arc(94.62,83.93) 94.86,83.89 94.92,83.89 arc(95.04,83.86) 95.14,83.79 95.37,83.57 arc(95.41,83.5) 95.43,83.42 95.43,83.3 arc(95.36,82.96) 95.17,82.67 v1(95.05,82.55)
PCIE0_RX0_P: length 43.2
  TOP w0.267: U9.AJ18 v1(95.85,83.35)
  L9-SIGNAL w0.127: TPX378.1 90.37,121.73 arc(90.22,121.51) 90.17,121.24 90.17,116.94 arc(90.4,115.76) 91.07,114.76 93.75,112.08 arc(94.3,111.26) 94.49,110.3 94.49,95.89 arc(94.41,95.5) 94.19,95.17 93.79,94.77 arc(93.53,94.39) 93.45,93.95 93.45,88.57 arc(93.51,88.24) 93.7,87.95 93.86,87.79 arc(94.14,87.38) 94.23,86.89 94.23,86.29 arc(94.27,86.2) 94.36,86.16 94.59,86.16 arc(94.77,85.98) 94.59,85.8 94.36,85.8 arc(94.27,85.77) 94.23,85.68 94.23,85.01 arc(94.3,84.68) 94.49,84.39 94.61,84.27 arc(94.73,84.19) 94.86,84.17 94.96,84.17 arc(95.15,84.13) 95.31,84.02 95.81,83.52 arc(95.84,83.48) 95.85,83.43 v1(95.85,83.35)
PCIE0_TX0_N: length 1
  BOTTOM w0.188: C227.2 TPX381.1
PCIE0_TX0_P: length 1
  BOTTOM w0.188: C226.2 TPX380.1
PCIE1_RX0_N: length 41.7
  TOP w0.267: U9.AH15 98.65,82.15 v1(98.25,82.55)
  L9-SIGNAL w0.127: TPX449.1 101.1,121.77 arc(101.26,121.53) 101.32,121.25 101.32,117.73 arc(101.04,116.32) 100.24,115.13 98.59,113.48 arc(98.1,112.74) 97.93,111.87 97.93,88.71 arc(97.98,88.45) 98.13,88.22 arc(98.22,88.09) 98.25,87.94 98.25,84.48 arc(98.31,84.18) 98.48,83.92 arc(98.55,83.83) 98.6,83.74 arc(98.62,83.65) 98.63,83.56 98.63,83.16 arc(98.59,82.95) 98.47,82.77 v1(98.25,82.55)
PCIE1_RX0_P: length 41.7
  TOP w0.267: v1(99.05,83.35) 99.45,82.95 U9.AJ14
  L9-SIGNAL w0.127: v1(99.05,83.35) 99.36,83.66 arc(99.41,83.78) 99.36,83.89 arc(99.3,83.94) 99.23,83.98 arc(99.21,83.99) 99.18,83.99 98.88,83.99 arc(98.81,84) 98.75,84.04 98.68,84.11 arc(98.57,84.28) 98.53,84.48 98.53,85.7 arc(98.55,85.75) 98.59,85.77 arc(98.77,85.95) 98.59,86.12 arc(98.55,86.14) 98.53,86.19 98.53,87.94 arc(98.47,88.2) 98.33,88.42 arc(98.24,88.55) 98.21,88.71 98.21,111.87 arc(98.36,112.64) 98.79,113.29 100.44,114.93 arc(101.3,116.22) 101.6,117.73 101.6,121.24 arc(101.65,121.51) 101.8,121.73 TPX448.1
PCIE1_RX1_N: length 40.6
  TOP w0.267: U9.AH16 v1(97.45,82.55)
  L9-SIGNAL w0.127: TPX450.1 97.26,121.8 arc(97.45,121.53) 97.51,121.2 97.51,116.43 arc(97.44,116.08) 97.24,115.79 arc(96.92,115.3) 96.8,114.73 96.8,84.35 arc(96.84,84.19) 96.93,84.05 96.99,83.99 arc(97.05,83.9) 97.07,83.8 97.07,83.3 arc(97.14,82.96) 97.33,82.67 v1(97.45,82.55)
PCIE1_RX1_P: length 40.6
  TOP w0.267: U9.AJ15 v1(98.25,83.35)
  L9-SIGNAL w0.127: TPX451.1 97.99,121.73 arc(97.84,121.51) 97.79,121.24 97.79,116.43 arc(97.7,115.98) 97.44,115.59 arc(97.18,115.19) 97.08,114.73 97.08,86.19 arc(97.1,86.14) 97.15,86.12 arc(97.33,85.95) 97.15,85.77 arc(97.1,85.75) 97.08,85.7 97.08,84.39 arc(97.1,84.3) 97.16,84.21 97.21,84.16 arc(97.43,84.01) 97.69,83.96 97.73,83.96 arc(97.93,83.92) 98.09,83.81 arc(98.21,83.64) 98.25,83.44 v1(98.25,83.35)
PCIE1_TX0_N: length 1
  BOTTOM w0.188: C224.2 TPX376.1
PCIE1_TX0_P: length 1
  BOTTOM w0.188: C225.2 TPX377.1
PCIE1_TX1_N: length 1
  BOTTOM w0.188: C223.2 TPX375.1
PCIE1_TX1_P: length 1
  BOTTOM w0.188: C222.2 TPX374.1
PCIE2_RX0_N: length 33.7
  TOP w0.267: U9.AH13 100.25,82.15 v1(100.65,82.55)
  L9-SIGNAL w0.127: TPX455.1 104.95,113.48 arc(105.1,113.25) 105.16,112.99 105.16,112.96 arc(105.11,112.72) 104.97,112.52 104.61,112.15 arc(104.16,111.49) 104.01,110.71 104.01,97.6 arc(103.87,96.89) 103.46,96.29 101.47,94.3 arc(101.08,93.71) 100.94,93.02 100.94,89.52 arc(100.99,89.3) 101.11,89.11 101.12,89.1 arc(101.16,89.05) 101.17,88.99 101.17,83.91 101.17,83.91 101.17,83.78 101.07,83.52 101.07,83.15 arc(101.03,82.98) 100.94,82.84 v1(100.65,82.55)
PCIE2_RX0_P: length 33.7
  TOP w0.267: v1(101.45,83.35) 101.05,82.95 U9.AJ12
  L9-SIGNAL w0.127: v1(101.45,83.35) 101.45,84.02 101.45,84.03 101.45,85.62 arc(101.47,85.66) 101.51,85.68 101.55,85.68 arc(101.73,85.86) 101.55,86.04 101.51,86.04 arc(101.47,86.05) 101.45,86.1 101.45,87.93 arc(101.5,88.06) 101.63,88.11 101.73,88.11 arc(101.9,88.29) 101.73,88.47 101.63,88.47 arc(101.5,88.52) 101.45,88.65 101.45,88.99 arc(101.41,89.15) 101.32,89.29 101.31,89.3 arc(101.24,89.4) 101.22,89.52 101.22,93.02 arc(101.34,93.6) 101.67,94.1 103.66,96.09 arc(104.12,96.79) 104.29,97.6 104.29,110.71 arc(104.42,111.38) 104.8,111.96 105.23,112.39 arc(105.38,112.61) 105.44,112.87 105.44,113.01 arc(105.49,113.28) 105.64,113.5 TPX454.1
PCIE2_RX1_N: length 32.4
  TOP w0.267: v1(101.45,82.55) 101.05,82.15 U9.AH12
  L9-SIGNAL w0.127: v1(101.45,82.55) 101.69,82.79 arc(101.83,82.99) 101.87,83.22 101.87,83.48 arc(101.92,83.72) 102.06,83.92 102.05,83.92 102.1,83.96 102.09,83.96 102.35,84.22 arc(102.51,84.45) 102.56,84.73 102.56,88.63 arc(102.62,88.95) 102.8,89.22 103,89.41 arc(103.19,89.69) 103.25,90.02 103.25,91.91 arc(103.4,92.65) 103.82,93.28 104.43,93.89 arc(104.81,94.46) 104.94,95.14 104.94,109.55 arc(105.03,109.99) 105.28,110.36 106.16,111.24 arc(106.33,111.5) 106.39,111.81 arc(106.35,112.02) 106.23,112.2 TPX373.1
PCIE2_RX1_P: length 32.4
  TOP w0.267: v1(102.25,83.35) 102.25,83.34 U9.AJ11
  L9-SIGNAL w0.127: TPX372.1 106.77,112.1 arc(106.7,111.98) 106.67,111.85 106.67,111.81 arc(106.59,111.39) 106.36,111.04 105.48,110.17 arc(105.29,109.89) 105.22,109.55 105.22,95.14 arc(105.07,94.36) 104.62,93.69 104.02,93.08 arc(103.66,92.55) 103.53,91.91 103.53,90.02 arc(103.44,89.59) 103.2,89.22 103,89.02 arc(102.88,88.84) 102.84,88.63 102.84,88.39 arc(102.88,88.3) 102.97,88.26 arc(103.1,88.21) 103.15,88.09 arc(103.1,87.96) 102.97,87.91 arc(102.88,87.87) 102.84,87.78 102.84,84.51 arc(102.86,84.41) 102.92,84.32 103.08,84.15 arc(103.14,84.02) 103.08,83.88 arc(103.01,83.83) 102.92,83.81 102.49,83.81 arc(102.32,83.74) 102.25,83.57 v1(102.25,83.35)
PCIE2_TX0_N: length 1
  BOTTOM w0.188: C213.2 TPX447.1
PCIE2_TX0_P: length 1
  BOTTOM w0.188: C212.2 TPX446.1
PCIE2_TX1_N: length 1
  BOTTOM w0.188: C221.2 TPX371.1
PCIE2_TX1_P: length 1
  BOTTOM w0.188: C220.2 TPX370.1
PG_LM5141: length 3.6
  TOP w0.203: U1007.21 v2(195.32,101.09) ; U1022.6 22.86,14.6 v2(21.97,13.71)
  BOTTOM w0.203: v2(195.32,101.09) 195.33,101.08 R1141.1
PG_LM5175: length 13.3
  TOP w0.203: 180.34,54.22 180.34,55.49 v2(179.32,55.49) ; TP1008.1 v2(179.32,59.43) 177.04,59.43 176.66,59.05 U1008.17
  L2-SIGNAL w0.133: TP1008.1 v2(179.32,59.43)
  BOTTOM w0.127: R1135.1 190.67,116.58 v2(190.25,116.15)
  BOTTOM w0.203: v2(179.32,59.43) v2(179.32,55.49)
PG_LM53603: length 3.9
  TOP w0.127: U1005.8 185.99,115.49 TP1005.1 ; R1006.2 175.9,130.16 v2(175.51,130.55) U1001.7
PMIC_MCU_INT#_R: length 8.4
  TOP w0.229: U9.G26 89.45,64.95 v1(89.45,64.95)
  L7-SIGNAL w0.097: v1(82.18,64.4) 85.27,64.4 86.18,65.31 89.08,65.31 v1(89.45,64.95)
PMIC_POWER_EN1: length 41.5
  TOP w0.229: U9.G23 91.85,64.95 v1(91.85,64.95)
  L2-SIGNAL w0.097: v1(91.85,64.95) 91.48,64.58 91.48,61.66 91.13,61.31 90.9,61.31 90.68,61.09 90.68,57.77 89.28,56.38 89.28,54.22 87,51.93 75.44,51.93 74.17,50.66 v1(74.17,38.22)
PMIC_PWR_EN1: length 1.5
  TOP w0.229: TP3019.1 135.78,84.7 135.74,84.66 R502.1
PMIC_REGEN1_3V3_OD: length 0.7
  TOP w0.127: U1008.1 v2(168.78,52.19)
PMICB_EN: length 16.1
  TOP w0.229: U29.20 v1(77.2,109.69) ; v1(89.03,115.56) R280.2
  L9-SIGNAL w0.097: v1(89.03,115.56) 85.34,115.56 78.99,109.21 77.68,109.21 v1(77.2,109.69)
PMICB_FB3: length 23.8
  TOP w0.229: R3150.1 R3151.1 v1(57.24,97.56) ; U29.49 v1(76.2,101.59)
  L9-SIGNAL w0.097: v1(57.24,97.56) 60.87,97.56 64.77,101.46 73.91,101.46 74.68,102.22 75.57,102.22 v1(76.2,101.59)
PMICB_FB4: length 24.6
  TOP w0.229: U29.50 v1(76.7,101.21) ; R3148.1 R3149.1 v1(57.24,96.09)
  L9-SIGNAL w0.097: v1(76.7,101.21) 74.8,101.21 74.55,100.95 64.77,100.95 60.96,97.14 58.29,97.14 v1(57.24,96.09)
PORZ: length 27
  TOP w0.229: v1(91.05,66.55) 91.05,66.55 U9.J24
  L5-PWR/GND w0.097: TPX282.1 68.33,60.95 75.82,60.95 77.98,63.11 84.12,63.11 84.71,63.7 88,63.7 88.08,63.62 88.39,63.62 88.56,63.79 88.8,63.79 89.01,64 89.01,64.23 89.36,64.59 89.6,64.59 89.81,64.8 89.81,65.03 90.16,65.39 90.4,65.39 90.61,65.6 90.61,66.1 v1(91.05,66.55)
PRG0_MDIO0_MDC: length 42.6
  TOP w0.191: U9.AA27 v1(88.65,76.95)
  L9-SIGNAL w0.097: TPX161.1 48.31,75.86 58.34,75.86 59.22,76.74 85.81,76.74 85.97,76.58 88.28,76.58 v1(88.65,76.95)
PRG0_MDIO0_MDIO: length 44.7
  TOP w0.191: U9.Y26 v1(89.45,76.15)
  L7-SIGNAL w0.097: v1(89.45,76.15) 89.01,76.58 85.97,76.58 85.72,76.82 55.12,76.82 54.1,75.81 46.74,75.81 TPX133.1
PRG0_PWM0_TZ_OUT: length 40.3
  TOP w0.191: v1(87.85,77.75) 88.25,77.35 U9.AB28
  BOTTOM w0.127: TPX184.1 49.17,76.72 54.02,76.72 54.05,76.69 83.17,76.69 83.84,77.36 87.45,77.36 v1(87.85,77.75)
PRG0_RGMII1_RD2: length 40.5
  TOP w0.191: U9.AE27 89.05,79.75 v1(88.65,80.15)
  L9-SIGNAL w0.097: TPX30.1 50.67,80.76 85.6,80.76 86.15,81.32 88,81.32 88.21,81.1 88.21,80.58 v1(88.65,80.15)
PRG0_RGMII1_RD3: length 41.1
  TOP w0.191: U9.AD26 89.85,78.95 v1(89.45,79.35)
  L9-SIGNAL w0.097: TPX6.1 50.93,77.97 51.14,77.97 51.15,77.98 51.47,77.98 51.48,77.97 52.41,77.97 52.42,77.98 52.74,77.98 52.75,77.97 53.68,77.97 53.69,77.98 54.01,77.98 54.15,77.84 85.22,77.84 86.31,78.93 89.03,78.93 v1(89.45,79.35)
PRG0_RGMII2_RD2: length 40.1
  TOP w0.191: U9.AD27 89.05,78.95 v1(88.65,79.35)
  L4-SIGNAL w0.097: v1(88.65,79.35) 88.22,79.78 88.22,80.3 88,80.52 86.6,80.52 83.81,83.31 51.94,83.31 TPX103.1
PRG0_RGMII2_RD3: length 40.1
  TOP w0.191: U9.AC25 90.65,78.15 v1(90.25,78.55)
  L4-SIGNAL w0.097: TPX180.1 53.21,80.76 67.18,80.76 70.2,77.74 85.76,77.74 86.16,78.15 89.85,78.15 v1(90.25,78.55)
PRG0_RGMII2_TD2: length 41.4
  TOP w0.191: v1(89.45,80.95) 89.85,80.55 U9.AF26
  L7-SIGNAL w0.097: TPX31.1 50.8,83.17 85.47,83.17 86.46,82.18 87.94,82.18 88.22,81.9 88.22,81.66 88.5,81.38 89.02,81.38 v1(89.45,80.95)
PRG0_RGMII2_TD3: length 45.5
  TOP w0.191: v1(90.25,80.15) 90.65,79.75 U9.AE25
  L7-SIGNAL w0.097: TPX7.1 46.62,79.25 54.01,79.25 54.02,79.24 69.09,79.24 70.38,80.53 89.87,80.53 v1(90.25,80.15)
PRG1_RGMII1_RD3: length 41.2
  TOP w0.191: U9.AJ23 v1(91.85,83.35)
  BOTTOM w0.127: v1(91.85,83.35) 91.85,83.81 91.47,84.19 56.39,84.19 55.37,83.17 53.34,83.17 TPX174.1
PRG1_UART0_RTS#: length 44.8
  TOP w0.191: v1(93.45,79.35) 93.85,78.95 U9.AD21
  L5-PWR/GND w0.097: v1(93.45,79.35) 93.06,78.96 91.67,78.96 91.47,78.76 91.47,78.37 91.24,78.15 90.85,78.15 90.63,78.37 90.63,78.78 90.47,78.93 86.81,78.93 85.82,77.94 57.05,77.94 56.53,78.47 51.7,78.47 TPX155.1
PWR_SW_CNTL_DSI0: length 3
  TOP w0.229: 95.94,24.13 v1(95.53,24.54) ; 95.94,24.13 96.19,24.38 U3011.3 ; 95.94,24.13 R3060.1
RESET_REQZ: length 54.5
  TOP w0.229: v1(87.85,61.75) 88.25,62.15 U9.C28
  L2-SIGNAL w0.097: TPX192.1 37.74,53.46 38,53.71 53.72,53.71 53.73,53.72 53.92,53.72 54.42,54.22 55.63,54.22 56.26,54.85 78.61,54.85 85.09,61.33 87.43,61.33 v1(87.85,61.75)
RESETSTATZ: length 56.4
  TOP w0.191: U9.T6 106.25,72.15 v1(106.25,72.15)
  L9-SIGNAL w0.097: v1(106.25,72.15) 106.63,72.53 106.63,73.98 106.81,74.16 108.05,74.16 108.25,73.95 108.25,73.45 108.66,73.04 112.45,73.04 116.57,77.16 137.2,77.16 142.37,72 154.69,72 TPX208.1
RGMII5_RD0: length 73.5
  TOP w0.229: v1(91.85,72.15) 91.86,72.15 U9.T23 ; v1(48.77,38.22) 48.74,38.24 U2011.26
  L9-SIGNAL w0.097: v1(91.85,72.15) 91.48,72.51 86.81,72.51 85.79,71.49 83.48,71.49 81.83,69.84 59.31,69.84 56.64,67.17 56.64,41.9 54.1,39.36 49.91,39.36 v1(48.77,38.22)
RGMII5_RD1: length 70.9
  TOP w0.229: v1(91.85,71.35) 91.86,71.35 U9.R23 ; v1(48.49,37.56) 48.27,37.79 48.27,37.82 48.24,37.85 U2011.25
  L9-SIGNAL w0.097: v1(91.85,71.35) 91.48,70.98 90.81,70.98 90.61,70.79 90.61,70.39 90.4,70.18 90,70.18 89.82,69.99 89.82,69.6 89.55,69.33 86.87,69.33 86.11,70.09 83.95,70.09 75.18,61.33 59.05,61.33 56.9,59.17 56.9,41.26 53.19,37.56 v1(48.49,37.56)
RGMII5_RD2: length 73
  TOP w0.191: U9.U24 91.06,73.74 v1(91.06,73.75)
  TOP w0.229: U2011.24 v1(47.74,38.09)
  L5-PWR/GND w0.097: v1(47.74,38.09) 48.25,38.6 48.92,38.6 49.18,38.34 50.42,38.34 50.8,38.72 50.8,39.87 52.07,41.14 54.99,41.14 59.31,45.46 59.31,48.84 59.32,48.85 59.32,49.17 59.31,49.18 59.31,62.09 61.09,63.87 61.09,67.17 63.46,69.55 82.13,69.55 83.57,70.98 89.66,70.98 89.89,71.21 89.89,71.5 90.1,71.71 90.39,71.71 90.69,72.01 90.69,72.64 91.06,73.01 v1(91.06,73.75)
RGMII5_RD3: length 76
  TOP w0.191: v1(88.66,73.75) 89.06,73.35 U9.U27
  TOP w0.229: v1(47.24,37.45) U2011.23
  L9-SIGNAL w0.097: v1(88.66,73.75) 88.02,73.11 85.5,73.11 84.95,73.66 75.56,73.66 74.17,75.05 62.1,75.05 56.39,69.33 56.39,42.41 53.72,39.74 49.66,39.74 48.26,38.34 48.26,37.96 47.75,37.45 v1(47.24,37.45)
RGMII5_RX_CTL: length 77.2
  TOP w0.191: v1(89.46,73.75) 89.46,73.74 U9.U26
  TOP w0.229: U2011.15 44.34,41.26 v1(43.43,41.26)
  L7-SIGNAL w0.097: v1(43.43,41.26) 54.48,41.26 55.37,42.15 55.37,45.96 56.64,47.23 56.64,69.46 60.97,73.79 76.44,73.79 77.6,72.63 80.77,72.63 81.52,73.38 89.09,73.38 v1(89.46,73.75)
RGMII5_RXC: length 67.9
  TOP w0.191: U9.U25 90.26,73.74 v1(90.26,73.75)
  TOP w0.229: U2011.27 v1(50.04,38.88)
  L5-PWR/GND w0.097: v1(90.26,73.75) 90.26,73.36 89.71,72.8 80.96,72.8 79.65,71.49 71.41,71.49 71.17,71.26 70.26,70.35 62.82,70.35 60.03,67.55 58.9,67.55 58.8,67.46 58.8,67.43 56.77,65.39 56.77,58.79 56.39,58.41 56.39,55.74 55.24,54.6 55.24,52.44 52.32,49.52 52.32,42.79 51.88,42.35 51.88,41.46 50.04,39.61 v1(50.04,38.88)
RGMII5_TD0: length 66
  TOP w0.191: v1(87.86,73.75) 88.26,73.35 U9.U28
  TOP w0.229: U2011.33 v1(50.93,42.27)
  L5-PWR/GND w0.097: v1(50.93,42.27) 51.99,43.33 51.99,51.85 56.01,55.87 56.01,58.92 56.52,59.43 56.52,69.97 60.32,73.78 69.34,73.78 71.37,71.74 79.5,71.74 81.05,73.3 87.4,73.3 v1(87.86,73.75)
RGMII5_TD1: length 68.9
  TOP w0.191: U9.V27 89.05,74.15 v1(88.65,74.55)
  TOP w0.229: U2011.32 v1(51.43,41.77)
  L9-SIGNAL w0.097: v1(51.43,41.77) 51.94,42.28 53.59,42.28 56.13,44.82 56.13,69.59 61.89,75.34 74.51,75.34 75.95,73.9 85.6,73.9 86.12,73.38 87.21,73.38 87.49,73.67 87.49,73.9 87.71,74.12 88.22,74.12 v1(88.65,74.55)
RGMII5_TD2: length 68.3
  TOP w0.191: U9.V29 v1(87.05,74.55)
  TOP w0.229: U2011.31 51.7,41.27 v1(52.26,41.84)
  L7-SIGNAL w0.097: v1(52.26,41.84) 53.02,41.84 54.61,43.42 54.61,46.09 56.13,47.61 56.13,72.13 59.69,75.68 76.96,75.68 78.36,74.28 85.09,74.28 85.35,74.55 v1(87.05,74.55)
RGMII5_TD3: length 69.5
  TOP w0.191: U9.V28 v1(87.85,74.55)
  TOP w0.229: v1(53.02,42.73) 53.02,41.58 52.21,40.77 U2011.30
  L9-SIGNAL w0.097: v1(53.02,42.73) 55.88,45.58 55.88,61.22 55.79,61.31 55.46,61.31 55.22,61.54 55.22,61.88 55.46,62.12 55.79,62.12 55.88,62.2 55.88,69.78 56.03,69.93 56.03,70.24 61.47,75.68 74.68,75.68 76.17,74.18 87.48,74.18 v1(87.85,74.55)
RGMII5_TX_CTL: length 69.6
  TOP w0.191: v1(91.86,73.75) 92.26,73.35 U9.U23
  TOP w0.229: U2011.29 v1(51.94,40.27)
  L5-PWR/GND w0.097: v1(51.94,40.27) 54.64,40.27 59.69,45.33 59.69,61.71 61.47,63.49 61.47,66.92 63.88,69.33 82.3,69.33 83.57,70.6 86.4,70.6 86.9,70.1 87.2,70.1 87.21,70.09 87.69,70.09 87.7,70.1 88,70.1 88.01,70.09 88.49,70.09 88.5,70.1 88.8,70.1 88.81,70.09 89.29,70.09 89.3,70.11 89.6,70.11 89.61,70.09 90.09,70.09 90.1,70.1 90.36,70.1 90.69,70.44 90.69,70.69 90.9,70.9 91.16,70.9 91.41,71.16 91.41,72.61 91.86,73.05 v1(91.86,73.75)
RGMII5_TXC: length 67.9
  TOP w0.191: v1(87.06,73.75) 87.46,73.35 U9.U29
  TOP w0.229: v1(54.24,41.76) 52.26,39.77 U2011.28
  L7-SIGNAL w0.097: v1(87.06,73.75) 78.13,73.75 76.71,75.17 61.85,75.17 56.39,69.71 56.39,47.36 54.99,45.96 54.99,42.51 v1(54.24,41.76)
SEL_SDIO_3V3_1V8N: length 25.3
  TOP w0.191: v1(107.85,75.35) 107.85,75.34 U9.W4
  L2-SIGNAL w0.102: v1(107.85,75.35) 108.26,75.76 110.41,75.76 111.25,76.6 120.68,76.6 122.66,78.58 125.53,78.58 126.72,79.77 129.72,79.77 v1(130.45,80.51)
SERDES0_REXT: length 0.6
  TOP w0.191: U9.AE18 96.25,79.75 v1(95.85,80.15)
SERDES1_REXT: length 0.6
  TOP w0.191: v1(100.65,80.15) 100.25,79.75 U9.AE13
SERDES2_REXT: length 1.3
  TOP w0.191: U9.AD13 100.25,78.95 v1(100.65,79.35)
  BOTTOM w0.229: v1(100.65,79.35) 100.52,79.21 100.05,79.21 R216.1
SERDES3_REXT: length 0.6
  TOP w0.191: v1(104.65,80.15) 104.65,80.14 U9.AE8
SERDES4_REXT: length 0.6
  TOP w0.229: U9.F9 v1(103.85,64.15)
SERDES4_RX0_N: length 39.7
  TOP w0.119: TP43.1 114.81,38.47 v1(115.32,38.98)
  TOP w0.191: U9.D9 v1(103.85,62.55)
  L5-PWR/GND w0.076: v1(103.85,62.55) 103.58,62.27 103.47,62.27 103.4,62.34 103.4,62.69 103.2,62.89 102.91,62.89 102.7,62.69 102.7,62.4 102.4,62.09 102.11,62.09 101.9,61.89 101.9,61.6 101.9,61.6 101.9,61.38 101.82,61.29 101.31,61.29 101.1,61.09 101.1,60.8 100.8,60.49 100.51,60.49 100.3,60.29 100.3,60 100.51,59.8 100.51,50.71 105.18,46.04 105.18,42.23 107.79,39.61 115.44,39.61 115.7,39.36 115.7,39.36 v1(115.32,38.98)
SERDES4_RX0_P: length 37.8
  TOP w0.119: v1(116.08,38.98) 116.71,38.35 TP42.1
  TOP w0.191: U9.C10 v1(103.05,61.75)
  L5-PWR/GND w0.076: v1(116.08,38.98) 116.08,39.26 115.53,39.82 107.87,39.82 105.38,42.31 105.38,46.12 100.71,50.79 100.71,59.71 101,60 101,60.22 101.37,60.6 101.6,60.6 101.9,60.9 101.9,61.09 102.05,61.24 102.05,61.24 102.11,61.29 102.29,61.29 102.6,61.6 102.6,62.01 102.79,62.2 103.26,62.2 103.33,62.13 103.33,62.02 v1(103.05,61.75)
SERDES4_RX1_N: length 28.2
  TOP w0.119: v1(112.4,41.52) 112.9,41.01 TP36.1
  TOP w0.191: U9.D8 v1(104.65,62.55)
  L5-PWR/GND w0.076: v1(104.65,62.55) 104.3,62.2 104.3,61.54 104.06,61.29 103.69,61.29 103.4,61.01 103.4,60.8 103.2,60.6 102.8,60.6 102.6,60.39 102.6,60 102.31,59.71 102.31,57.53 112.09,47.75 112.09,42.02 112.12,41.99 112.12,41.8 v1(112.4,41.52)
SERDES4_RX1_P: length 27.4
  TOP w0.119: v1(111.64,41.52) 111,40.88 TP35.1
  TOP w0.191: U9.C9 v1(103.85,61.75)
  L5-PWR/GND w0.076: v1(111.64,41.52) 111.92,41.8 111.92,41.91 111.89,41.94 111.89,47.67 102.11,57.45 102.11,59.8 101.9,60 101.9,60.29 102.11,60.49 102.41,60.49 102.6,60.68 102.6,61.09 102.91,61.4 103.5,61.4 v1(103.85,61.75)
SERDES4_RX2_N: length 37.8
  TOP w0.119: v1(125.61,37.71) 126.24,37.08 TP39.1
  TOP w0.191: U9.D6 v1(106.25,62.55)
  L5-PWR/GND w0.076: v1(125.61,37.71) 125.35,37.97 125.35,38.12 124.92,38.55 124.79,38.55 124.79,38.55 124.75,38.55 124.75,38.55 123.27,38.55 103.91,57.91 103.91,59.71 104.2,60 104.2,60.29 104.51,60.6 104.8,60.6 105,60.8 105,61.18 105.12,61.29 105.57,61.29 105.91,61.63 105.91,62.2 v1(106.25,62.55)
SERDES4_RX2_P: length 36.9
  TOP w0.119: v1(124.84,37.71) 124.33,37.2 TP37.1
  TOP w0.191: U9.C7 v1(105.45,61.75)
  L5-PWR/GND w0.076: v1(105.45,61.75) 105.45,61.72 105.22,61.5 105.03,61.5 104.83,61.29 104.51,61.29 104.3,61.09 104.3,60.8 104.31,60.79 104.31,60.69 104.12,60.49 103.71,60.49 103.5,60.29 103.5,60 103.71,59.8 103.71,57.83 123.19,38.34 124.84,38.34 125.09,38.09 125.09,37.96 v1(124.84,37.71)
SERDES4_RX3_N: length 35.1
  TOP w0.119: v1(125.61,40.5) 126.24,39.87 TP40.1
  TOP w0.191: U9.D5 v1(107.05,62.55)
  L5-PWR/GND w0.076: v1(125.61,40.5) 125.37,40.74 125.37,40.96 124.8,41.52 122.68,41.52 105.54,58.66 105.54,59.74 105.8,60 105.8,60.32 106.07,60.6 106.4,60.6 106.6,60.8 106.6,61.2 106.8,61.4 107.2,61.4 107.4,61.6 107.4,61.89 107.2,62.09 106.85,62.09 106.78,62.16 106.78,62.27 v1(107.05,62.55)
SERDES4_RX3_P: length 34.3
  TOP w0.119: TP38.1 124.33,39.99 v1(124.84,40.5)
  TOP w0.191: v1(106.25,61.75) 105.85,62.14 U9.C6
  L5-PWR/GND w0.076: v1(124.84,40.5) 125.09,40.75 125.09,40.94 124.72,41.32 122.6,41.32 105.33,58.58 105.33,59.75 105.1,59.97 105.1,60.29 105.31,60.49 105.6,60.49 105.91,60.8 105.91,61.09 106.11,61.29 106.41,61.29 106.71,61.59 106.71,61.95 106.64,62.02 106.53,62.02 v1(106.25,61.75)
SGMII2_RX0_N: length 41.2
  TOP w0.122: v1(95.85,82.55) 96.25,82.15 U9.AH18
  L9-SIGNAL w0.099: v1(95.85,82.55) 96.13,82.83 arc(96.24,83) 96.28,83.2 96.28,83.4 arc(96.25,83.56) 96.16,83.69 95.76,84.09 arc(95.5,84.49) 95.4,84.96 95.4,88 arc(95.33,88.15) 95.3,88.31 95.3,112.26 arc(95.2,112.78) 94.9,113.22 94.17,113.96 arc(93.79,114.52) 93.66,115.19 93.66,121.29 arc(93.6,121.58) 93.44,121.81 TPX443.1
SGMII2_RX0_P: length 41.3
  TOP w0.122: v1(96.65,83.35) 96.86,83.16 96.87,83.11 U9.AJ17
  L9-SIGNAL w0.099: TPX442.1 94.18,121.72 arc(94.04,121.52) 93.99,121.27 93.99,115.19 arc(94.09,114.65) 94.4,114.19 95.14,113.46 arc(95.5,112.91) 95.63,112.26 95.63,88.31 arc(95.64,88.25) 95.67,88.19 arc(95.74,88.13) 95.84,88.11 arc(96,87.94) 95.84,87.78 arc(95.76,87.75) 95.73,87.67 95.73,86.24 arc(95.76,86.17) 95.83,86.14 95.98,86.14 arc(96.14,85.98) 95.98,85.81 95.83,85.81 arc(95.76,85.79) 95.73,85.72 95.73,84.96 arc(95.8,84.61) 96,84.32 96.42,83.9 arc(96.59,83.65) v1(96.65,83.35)
SGMII2_TX0_N: length 1
  BOTTOM w0.119: C215.2 TPX441.1
SGMII2_TX0_P: length 1
  BOTTOM w0.119: C214.2 TPX440.1
SOC_EMU0: length 43.4
  TOP w0.229: J1011.19 v1(53.8,59.6) ; v1(89.45,61.75) 89.85,62.15 U9.C26
  L7-SIGNAL w0.097: v1(58.8,59.81) 58.8,59.42 60.71,57.51 60.71,57.27 62.54,55.43 79.83,55.43 85.77,61.38 89.08,61.38 89.44,61.75 v1(89.45,61.75)
  BOTTOM w0.229: 53.09,59.81 53.29,59.6 v1(53.8,59.6) 58.14,59.6 58.34,59.81 v1(58.8,59.81)
SOC_EMU1: length 38.7
  TOP w0.229: U9.B29 87.45,61.35 v1(87.05,60.95) ; v1(54.23,60.19) 54.14,60.1 J1011.21
  L4-SIGNAL w0.097: v1(87.05,60.95) 84.64,60.95 84.17,60.47 74.96,60.47 74.49,60.95 61.08,60.95 59.05,58.92 55.5,58.92 v1(54.23,60.19)
  BOTTOM w0.229: 53.09,61.08 53.62,60.54 53.88,60.54 v1(54.23,60.19)
SOC_EXTINTN: length 50.4
  TOP w0.127: R43.1 TPX206.1
  TOP w0.191: v1(95.85,78.55) 96.25,78.15 U9.AC18
  L9-SIGNAL w0.097: 83.31,87.75 81.03,90.03 57.02,90.03 56.77,90.29 TPX206.1 ; 92.8,80.58 92.89,80.58 93.08,80.39 93.08,80 93.3,79.78 93.53,79.78 93.88,79.43 93.88,79.2 94.16,78.92 95.48,78.92 v1(95.85,78.55)
  L9-SIGNAL w0.102: 83.31,87.75 87.76,87.75 91.29,84.21 91.75,84.21 92.28,83.68 92.28,83.5 92.28,83.5 92.28,83.2 92.28,83.19 92.28,82.7 92.28,82.7 92.28,82.4 92.28,82.39 92.28,81.9 92.28,81.9 92.28,81.6 92.28,81.59 92.28,81.1 92.28,81.1 92.28,80.8 92.5,80.58 92.8,80.58 92.8,80.58
SOC_I2C2_SCL: length 50.9
  TOP w0.191: U9.AA1 110.25,76.94 v1(110.25,76.95)
  TOP w0.229: R54.2 TPX296.1
  L5-PWR/GND w0.097: TPX296.1 155.32,75.17 142.62,75.17 137.8,80 121.7,80 120.61,78.91 117.53,78.91 116.08,77.46 111.25,77.46 110.74,76.95 v1(110.25,76.95)
SOC_I2C2_SDA: length 43.5
  TOP w0.191: v1(107.05,77.75) 107.05,77.74 U9.AB5
  TOP w0.229: R25.2 TPX203.1
  L9-SIGNAL w0.102: v1(107.05,77.75) 106.65,78.15 106.65,78.73 106.4,78.98 106.1,78.98 105.88,79.2 105.88,79.2 105.82,79.26 105.82,79.5 105.82,79.51 105.82,79.51 105.62,79.72 105.61,79.72 105.61,79.72 105.31,79.72 105.05,79.97 105.05,83.48 105.31,83.73 105.71,83.73 107.01,85.03 107.01,87.26 107.77,88.03 107.77,90.11 109.65,91.99 109.65,110.2 109.66,110.2 109.66,110.71 109.66,110.71 109.66,111.8 TPX203.1
SOC_MCU_OSPI0_CLK_R: length 10.1
  TOP w0.229: U9.E20 94.65,63.75 v1(94.25,63.35)
  L9-SIGNAL w0.097: v1(94.25,63.35) 94.28,63.35 94.68,62.94 94.68,59.91 95.07,59.51 95.07,58.69 95.38,58.38 95.5,58.26 95.5,56.46 v1(94.87,55.83)
  BOTTOM w0.229: v1(94.87,55.83) 94.27,55.83 93.9,55.46 R247.1
SOC_MCU_OSPI0_LBCLKO_R: length 9.9
  TOP w0.229: v1(93.45,61.75) 93.45,61.75 U9.C21
  L9-SIGNAL w0.097: v1(94.81,56.8) 94.81,56.6 94.95,56.46 95.1,56.46 95.21,56.57 95.29,56.65 95.29,58.17 94.86,58.6 94.86,59.42 94.62,59.66 94.06,59.66 93.86,59.87 93.86,61.92 93.76,62.02 93.55,62.02 93.45,61.92 v1(93.45,61.75)
  BOTTOM w0.229: R264.1 93.91,56.56 94.21,56.26 94.6,56.26 94.81,56.47 v1(94.81,56.8)
SOC_PORZ_OUT: length 47.2
  TOP w0.191: U9.U1 109.85,73.35 v1(110.25,73.75)
  TOP w0.229: R80.1 TPX278.1
  L7-SIGNAL w0.097: TPX278.1 142.62,72.51 137.41,77.71 130.56,77.71 129.79,78.48 120.52,78.48 118.24,76.19 114.55,76.19 112.11,73.75 v1(110.25,73.75)
SOC_PWR_EN: length 0.7
  TOP w0.229: U27.20 v1(128.05,98.15)
SOC_SAFETY_ERRZ: length 0.7
  TOP w0.229: R56.2 TPX230.1
SOC_SAFETY_ERRZ_27020508: length 2.1
  BOTTOM w0.229: R276.1 v1(135.64,92.7)
SOC_SERDES0_REFCLK_N: length 44.1
  TOP w0.122: U9.AE17 97.05,79.75 v1(96.65,80.15)
  L4-SIGNAL w0.099: TPX392.1 91.63,120.77 arc(91.67,120.76) 91.7,120.74 91.74,120.7 arc(91.8,120.61) 91.82,120.5 91.82,117.79 arc(91.9,117.39) 92.13,117.05 93.51,115.67 arc(93.95,115.01) 94.11,114.23 94.11,101.71 arc(94.46,99.91) 95.48,98.37 arc(95.49,98.35) 95.51,98.34 96.05,97.79 arc(96.28,97.44) 96.37,97.03 96.37,88.71 arc(96.44,88.34) 96.65,88.02 96.65,88.02 arc(96.78,87.83) 96.82,87.61 96.82,84.21 arc(96.8,84.1) 96.74,84.01 96.41,83.68 arc(96.31,83.53) 96.28,83.35 96.28,80.06 arc(96.32,79.94) 96.44,79.9 arc(96.59,79.96) 96.65,80.11 v1(96.65,80.15)
SOC_SERDES0_REFCLK_P: length 44.1
  TOP w0.122: v1(97.45,79.35) 97.85,78.95 U9.AD16
  L4-SIGNAL w0.099: v1(97.45,79.35) 97.28,79.52 arc(97.13,79.74) 97.08,80 97.08,87.61 arc(97.02,87.93) 96.83,88.2 96.83,88.2 arc(96.68,88.44) 96.62,88.71 96.62,97.03 arc(96.52,97.54) 96.23,97.97 95.69,98.52 arc(95.67,98.53) 95.66,98.54 arc(94.7,100) 94.36,101.71 94.36,114.23 arc(94.19,115.11) 93.69,115.85 92.31,117.23 arc(92.14,117.49) 92.07,117.79 92.07,120.5 arc(92.09,120.58) 92.14,120.65 arc(92.27,120.74) 92.42,120.77 TPX393.1
SOC_SERDES1_REFCLK_N: length 43.4
  TOP w0.122: v1(99.05,80.15) 99.45,79.75 U9.AE14
  L4-SIGNAL w0.099: TPX423.1 96.19,120.77 arc(96.01,120.71) 95.9,120.55 95.89,120.46 95.89,119.47 arc(96,118.91) 96.32,118.43 97.08,117.67 arc(97.66,116.8) 97.87,115.77 97.87,88.83 arc(97.89,88.7) 97.97,88.59 arc(98.32,88.05) 98.45,87.42 98.45,84 arc(98.47,83.89) 98.53,83.81 98.55,83.78 arc(98.63,83.67) 98.65,83.54 98.65,79.97 arc(98.7,79.85) 98.83,79.8 98.89,79.8 arc(99.01,79.84) 99.05,79.96 99.05,80.15 v1(99.05,80.15)
SOC_SERDES1_REFCLK_P: length 43.4
  TOP w0.122: v1(98.25,79.35) 98.65,78.95 U9.AD15
  L4-SIGNAL w0.099: TPX422.1 95.33,120.77 arc(95.51,120.71) 95.62,120.55 95.63,120.5 95.63,120.48 95.63,119.47 arc(95.76,118.81) 96.14,118.25 96.9,117.49 arc(97.43,116.7) 97.61,115.77 97.61,88.83 arc(97.66,88.6) 97.79,88.41 arc(98.09,87.95) 98.2,87.42 98.2,83.99 arc(98.19,83.94) 98.16,83.9 97.94,83.68 arc(97.89,83.6) 97.87,83.5 97.87,80.28 arc(97.97,79.77) v1(98.25,79.35)
SOC_SERDES2_REFCLK_N: length 43.4
  TOP w0.122: U9.AE11 102.25,80.14 v1(102.25,80.15)
  L4-SIGNAL w0.099: TPX427.1 99.91,120.77 arc(99.8,120.75) 99.72,120.69 99.7,120.67 arc(99.67,120.62) 99.65,120.56 arc(99.65,120.55) 99.64,120.55 arc(99.64,120.54) 99.64,120.53 99.64,119.58 arc(99.55,119.08) 99.26,118.66 arc(99.15,118.49) 99.11,118.29 99.11,102.57 arc(99.19,102.16) 99.42,101.81 99.96,101.28 arc(100.5,100.47) 100.69,99.52 100.69,89.51 arc(100.79,88.96) 101.1,88.5 101.12,88.48 arc(101.36,88.12) 101.45,87.7 101.45,84.03 arc(101.45,83.99) 101.46,83.94 arc(101.49,83.88) 101.53,83.83 101.72,83.64 arc(101.79,83.53) 101.82,83.39 101.82,80.15 arc(101.85,80.02) 101.93,79.92 arc(102,79.89) 102.08,79.91 102.13,79.93 arc(102.23,80.02) v1(102.25,80.15)
